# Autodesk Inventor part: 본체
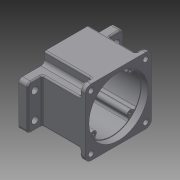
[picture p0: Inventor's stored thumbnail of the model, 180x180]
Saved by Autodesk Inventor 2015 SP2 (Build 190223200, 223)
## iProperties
Created: 2015-06
Part Number: 본체
Material: 일반
Document SubType Name: Modeling
Designer: AMC
Density: 1 g/cm^3
Appearance: 기본값
Author: AMC
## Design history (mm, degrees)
sketch "스케치1"
  geometry: L1 (0, 0)-(90, 0); L2 (90, 0)-(90, 90); L3 (90, 90)-(0, 90); L4 (0, 90)-(0, 0)
  constraints: 8 end point, 2 parallel, 1 horizontal, 1 perpendicular
  dimensions: "d0" = 90 distance of L3.end L2.end; "d1" = 90 distance of L2.end L1.end
extrude "돌출1" new body sketch "스케치1" distance "d2" = 58; taper "d3" = 0 deg
sketch "스케치2"
  geometry: L1 (0, 0)-(-90, 0) reference; L2 (-90, 0)-(-90, 90) reference; L3 (-90, 90)-(0, 90) reference; L4 (0, 90)-(0, 0) reference; L5 (20, 75)-(20, 15); L6 (-110, 15)-(-110, 75); L7 (-90, 90)-(0, 90) reference; L8 (0, 0)-(-90, 0) reference; L9 (-75, 90)-(-15, 90); L10 (-15, 0)-(-75, 0); L11 (-110, 75)-(-75, 75); L12 (-15, 75)-(20, 75); L13 (20, 15)-(-15, 15); L14 (-75, 15)-(-110, 15); L15 (-75, 0)-(-75, 15); L16 (-75, 75)-(-75, 90); L17 (-15, 90)-(-15, 75); L18 (-15, 15)-(-15, 0); 10 further points
  constraints: 24 end point, 10 parallel, 8 midpoint, 4 perpendicular, 3 horizontal, 2 horizontal alignment, 2 point on line, 2 vertical alignment, 1 coincident
  dimensions: "d4" = 130 distance of L5.end L6.start; "d5" = 60 distance of L5.start L5.end; "d6" = 60 distance of L10.start L10.end; "d7" = 35 distance between parallel lines of L6 L16; "d8" = 60 distance of L6.start L6.end; "d9" = 90 distance of L10.start L9.end; "d10" = 35 distance between parallel lines of L5 L18
extrude "돌출2" join sketch "스케치2" distance "d11" = 12; taper "d12" = 0 deg
fillet "모깎기1" dims "d13" = 8
fillet "모깎기2" dims "d14" = 5
sketch "스케치3"
  geometry: L1 (-75, 80)-(-75, 90) reference; L2 (-75, 90)-(-82, 90) reference; L3 (-90, 82)-(-90, 75) reference; L4 (-90, 75)-(-80, 75) reference; L5 (-80, 15)-(-90, 15) reference; L6 (-90, 15)-(-90, 8) reference; L7 (-82, 0)-(-75, 0) reference; L8 (-75, 0)-(-75, 10) reference; L9 (-15, 10)-(-15, 0) reference; L10 (-15, 0)-(-8, 0) reference; L11 (0, 8)-(0, 15) reference; L12 (0, 15)-(-10, 15) reference; L13 (-10, 75)-(0, 75) reference; L14 (0, 75)-(0, 82) reference; L15 (-8, 90)-(-15, 90) reference; L16 (-15, 90)-(-15, 80) reference; A1 r 5 centre (-80, 80) between (-80, 75) and (-75, 80) reference; A2 r 8 centre (-82, 82) between (-82, 90) and (-90, 82) reference; A3 r 5 centre (-80, 10) between (-75, 10) and (-80, 15) reference; A4 r 8 centre (-82, 8) between (-90, 8) and (-82, 0) reference; A5 r 5 centre (-10, 10) between (-10, 15) and (-15, 10) reference; A6 r 8 centre (-8, 8) between (-8, 0) and (0, 8) reference; A7 r 5 centre (-10, 80) between (-15, 80) and (-10, 75) reference; A8 r 8 centre (-8, 82) between (0, 82) and (-8, 90) reference; 1 further point
extrude "돌출3" cut sketch "스케치3" distance "d15" = 51; taper "d16" = 0 deg
sketch "스케치4"
  geometry: L1 (75, 90)-(75, 80) reference; L2 (80, 75)-(110, 75) reference; L3 (110, 75)-(110, 15) reference; L4 (110, 15)-(80, 15) reference; L5 (75, 10)-(75, 0) reference; L6 (75, 0)-(15, 0) reference; L7 (15, 0)-(15, 10) reference; L8 (10, 15)-(-20, 15) reference; L9 (-20, 15)-(-20, 75) reference; L10 (-20, 75)-(10, 75) reference; L11 (15, 80)-(15, 90) reference; L12 (15, 90)-(75, 90) reference; L13 (0, 15)-(0, 75) reference; A1 r 5 centre (80, 80) between (75, 80) and (80, 75) reference; A2 r 5 centre (80, 10) between (80, 15) and (75, 10) reference; A3 r 5 centre (10, 10) between (15, 10) and (10, 15) reference; A4 r 5 centre (10, 80) between (10, 75) and (15, 80) reference; 4 further points
  constraints: 2 midpoint, 1 horizontal alignment, 1 vertical alignment
hole "구멍1" sketch "스케치4" at (45, 45) diameter "d17" = 78; stored, may be unused: countersink angle "d21" = 90 deg, drill point angle "d23" = 0 deg; dims "d18" = 6, "d19" = 80, "d20" = 9, "d22" = 61
fillet "모깎기3" dims "d24" = 5
sketch "스케치5"
  geometry: L1 (-82, 90)-(-8, 90) reference; L2 (-45, 90)-(-45, 0); L3 (-110, 70)-(-110, 20) reference; L4 (-90, 75)-(-105, 75) reference; C1 r 4.5 at (-100, 62.5); C2 r 4.5 at (-100, 27.5); C3 r 4.5 at (10, 62.5); C4 r 4.5 at (10, 27.5); 1 further point
  constraints: 4 centre point, 2 end point, 2 symmetric about line, 1 midpoint, 1 vertical, 2 other
  dimensions: "d25" = 9 diameter of C1; "d26" = 9 diameter of C2; "d27" = 35 distance of C2.centre C1.centre; "d29" = 10 distance from line of C1.centre L3; "d30" = 10 distance from line of L3 C2.centre; "d31" = 12.5 distance from line of C1.centre L4
extrude "돌출4" cut sketch "스케치5" stored distance "d33" = 51; taper "d34" = 0 deg
sketch "스케치6"
  geometry: L1 (-75, 90)-(-75, 80) reference; L2 (-82, 90)-(-75, 90) reference; L3 (-90, 75)-(-90, 82) reference; L4 (-80, 75)-(-90, 75) reference; L5 (0, 75)-(-10, 75) reference; L6 (0, 82)-(0, 75) reference; L7 (-15, 90)-(-8, 90) reference; L8 (-15, 80)-(-15, 90) reference; L9 (-15, 0)-(-15, 10) reference; L10 (-8, 0)-(-15, 0) reference; L11 (0, 15)-(0, 8) reference; L12 (-10, 15)-(0, 15) reference; L13 (-90, 15)-(-80, 15) reference; L14 (-90, 8)-(-90, 15) reference; L15 (-75, 0)-(-82, 0) reference; L16 (-75, 10)-(-75, 0) reference; C1 r 3.5 at (-82, 82); C2 r 3.5 at (-8, 82); C3 r 3.5 at (-8, 8); C4 r 3.5 at (-82, 8); A1 r 5 centre (-80, 80) between (-80, 75) and (-75, 80) reference; A2 r 8 centre (-82, 82) between (-82, 90) and (-90, 82) reference; A3 r 5 centre (-10, 80) between (-15, 80) and (-10, 75) reference; A4 r 8 centre (-8, 82) between (0, 82) and (-8, 90) reference; A5 r 5 centre (-10, 10) between (-10, 15) and (-15, 10) reference; A6 r 8 centre (-8, 8) between (-8, 0) and (0, 8) reference; A7 r 5 centre (-80, 10) between (-75, 10) and (-80, 15) reference; A8 r 8 centre (-82, 8) between (-90, 8) and (-82, 0) reference; 1 further point
  constraints: 4 centre point, 4 coincident
  dimensions: "d35" = 7 diameter of C1; "d36" = 7 diameter of C2; "d37" = 7 diameter of C3; "d38" = 7 diameter of C4
extrude "돌출5" cut sketch "스케치6" stored distance "d39" = 51; taper "d40" = 0 deg
sketch "스케치7"
  geometry: L1 (0, 0)-(0, 66.237); L2 (0, 0)-(-52.363, 52.363); L3 (-21.763, 27.411)-(-25.096, 31.148); L4 (-27.411, 21.763)-(-31.148, 25.096); C1 r 39 at (0, 0) reference; A1 r 40 centre (0, 0) between (-31.148, 25.096) and (-25.096, 31.148) reference; A2 r 35 centre (0, 0) between (-24.749, 24.749) and (-21.763, 27.411); A3 r 4 centre (-24.749, 24.749) between (-27.411, 21.763) and (-21.763, 27.411); 1 further point
  constraints: 8 end point, 7 point on circle, 2 centre point, 2 coincident, 2 tangent, 1 point on line, 1 vertical
  dimensions: "d41" = 70 diameter of A2; "d42" = 45 deg angle of L1 L2; "d43" = 8 diameter of A3
extrude "돌출6" join sketch "스케치7" stored distance "d44" = 51; taper "d45" = 0 deg
fillet "모깎기4" dims "d49" = 3.5
fillet "모깎기5" dims "d50" = 2
sketch "스케치8"
  geometry: L1 (-27.507, 21.849)-(-27.411, 21.763) reference; L2 (-21.763, 27.411)-(-21.849, 27.507) reference; L3 (21.849, 27.507)-(21.763, 27.411) reference; L4 (27.411, 21.763)-(27.507, 21.849) reference; L5 (27.507, -21.849)-(27.411, -21.763) reference; L6 (21.763, -27.411)-(21.849, -27.507) reference; L7 (-21.849, -27.507)-(-21.763, -27.411) reference; L8 (-27.411, -21.763)-(-27.507, -21.849) reference; C1 r 40 at (0, 0) reference; A1 r 3.5 centre (-29.836, 19.237) between (-27.507, 21.849) and (-32.778, 21.133) reference; A2 r 4 centre (-24.749, 24.749) between (-27.411, 21.763) and (-21.763, 27.411) reference; A3 r 3.5 centre (-19.237, 29.836) between (-21.133, 32.778) and (-21.849, 27.507) reference; A4 r 39 centre (0, 0) between (21.133, 32.778) and (-21.133, 32.778) reference; A5 r 3.5 centre (19.237, 29.836) between (21.849, 27.507) and (21.133, 32.778) reference; A6 r 4 centre (24.749, 24.749) between (21.763, 27.411) and (27.411, 21.763) reference; A7 r 3.5 centre (29.836, 19.237) between (32.778, 21.133) and (27.507, 21.849) reference; A8 r 39 centre (0, 0) between (32.778, -21.133) and (32.778, 21.133) reference; A9 r 3.5 centre (29.836, -19.237) between (27.507, -21.849) and (32.778, -21.133) reference; A10 r 4 centre (24.749, -24.749) between (27.411, -21.763) and (21.763, -27.411) reference; A11 r 3.5 centre (19.237, -29.836) between (21.133, -32.778) and (21.849, -27.507) reference; A12 r 39 centre (0, 0) between (-21.133, -32.778) and (21.133, -32.778) reference; A13 r 3.5 centre (-19.237, -29.836) between (-21.849, -27.507) and (-21.133, -32.778) reference; A14 r 4 centre (-24.749, -24.749) between (-21.763, -27.411) and (-27.411, -21.763) reference; A15 r 3.5 centre (-29.836, -19.237) between (-32.778, -21.133) and (-27.507, -21.849) reference; A16 r 39 centre (0, 0) between (-32.778, 21.133) and (-32.778, -21.133) reference; 1 further point
hole "구멍2" sketch "스케치8" at (24.749, -24.749), (24.749, 24.749), (-24.749, 24.749), (-24.749, -24.749) diameter "d51" = 3.242; stored, may be unused: countersink angle "d55" = 90 deg, drill point angle "d57" = 118 deg; dims "d52" = 12, "d53" = 80, "d54" = 9, "d56" = 15
sketch "스케치9"
  geometry: L1 (20.271, -28.742)-(20.356, -28.838) reference; L2 (28.838, -20.356)-(28.742, -20.271) reference; L3 (28.742, 20.271)-(28.838, 20.356) reference; L4 (20.356, 28.838)-(20.271, 28.742) reference; L5 (-20.271, 28.742)-(-20.356, 28.838) reference; L6 (-28.838, 20.356)-(-28.742, 20.271) reference; L7 (-28.742, -20.271)-(-28.838, -20.356) reference; L8 (-20.356, -28.838)-(-20.271, -28.742) reference; A1 r 20.5 centre (0, 11) between (7.402, -8.117) and (-7.402, -8.117); A2 r 37 centre (0, 0) between (-20.049, -31.097) and (20.049, -31.097) reference; A3 r 6 centre (24.749, -24.749) between (28.742, -20.271) and (20.271, -28.742) reference; A4 r 37 centre (0, 0) between (31.097, -20.049) and (31.097, 20.049) reference; A5 r 6 centre (24.749, 24.749) between (20.271, 28.742) and (28.742, 20.271) reference; A6 r 37 centre (0, 0) between (20.049, 31.097) and (-20.049, 31.097) reference; A7 r 6 centre (-24.749, 24.749) between (-28.742, 20.271) and (-20.271, 28.742) reference; A8 r 37 centre (0, 0) between (-31.097, 20.049) and (-31.097, -20.049) reference; A9 r 6 centre (-24.749, -24.749) between (-20.271, -28.742) and (-28.742, -20.271) reference; A10 r 14 centre (0, -20) between (-7.402, -8.117) and (7.402, -8.117); A11 r 1.5 centre (19.237, -29.836) between (20.049, -31.097) and (20.356, -28.838) reference; A12 r 1.5 centre (29.836, -19.237) between (28.838, -20.356) and (31.097, -20.049) reference; A13 r 1.5 centre (29.836, 19.237) between (31.097, 20.049) and (28.838, 20.356) reference; A14 r 1.5 centre (19.237, 29.836) between (20.356, 28.838) and (20.049, 31.097) reference; A15 r 1.5 centre (-19.237, 29.836) between (-20.049, 31.097) and (-20.356, 28.838) reference; A16 r 1.5 centre (-29.836, 19.237) between (-28.838, 20.356) and (-31.097, 20.049) reference; A17 r 1.5 centre (-29.836, -19.237) between (-31.097, -20.049) and (-28.838, -20.356) reference; A18 r 1.5 centre (-19.237, -29.836) between (-20.356, -28.838) and (-20.049, -31.097) reference; 1 further point
  constraints: 4 point on circle, 2 centre point, 2 vertical alignment
  dimensions: "d58" = 41 diameter of A1; "d59" = 28 diameter of A10; "d60" = 11 distance of A2.centre A1.centre; "d61" = 20 distance of A2.centre A10.centre
extrude "돌출7" join sketch "스케치9" distance "d62" = 7; taper "d63" = 0 deg
sketch "스케치10"
  geometry: C1 r 25 at (-45, 56); A1 r 20.5 centre (-45, 56) between (-37.598, 36.883) and (-52.402, 36.883) reference; 1 further point
  constraints: 1 centre point, 1 coincident
  dimensions: "d64" = 50 diameter of C1
extrude "돌출8" join sketch "스케치10" distance "d65" = 7; taper "d66" = 0 deg
sketch "스케치11"
  geometry: C1 r 25 at (0, 0) reference; 1 further point
hole "구멍3" sketch "스케치11" at (0, 0) diameter "d67" = 25; stored, may be unused: countersink angle "d71" = 90 deg, drill point angle "d73" = 0 deg; dims "d68" = 12, "d69" = 32, "d70" = 8, "d72" = 13
sketch "스케치12"
  geometry: C1 r 12.5 at (0, 11) reference; A1 r 14 centre (0, -20) between (-7.402, -8.117) and (7.402, -8.117) reference; A2 r 20.5 centre (0, 11) between (7.402, -8.117) and (-7.402, -8.117) reference; 1 further point
hole "구멍4" sketch "스케치12" at (0, -20) diameter "d74" = 19; stored, may be unused: countersink angle "d78" = 90 deg, drill point angle "d80" = 0 deg; dims "d75" = 12, "d76" = 22, "d77" = 7, "d79" = 8
sketch "스케치13"
  geometry: C1 r 11 at (0, -20) reference; C2 r 12.5 at (0, 11) reference; C3 r 17.5 at (0, 11); A1 r 14 centre (0, -20) between (-7.402, -8.117) and (7.402, -8.117) reference; A2 r 20.5 centre (0, 11) between (7.402, -8.117) and (-7.402, -8.117) reference; 1 further point
  constraints: 1 centre point, 1 coincident
  dimensions: "d81" = 35 diameter of C3
extrude "돌출9" cut sketch "스케치13" distance "d82" = 10; taper "d83" = 0 deg
chamfer "모따기1" distance "d84" = 1; stored, may be unused: second distance "d85" = 2, angle "d86" = 45 deg
fillet "모깎기6" dims "d87" = 0.3
fillet "모깎기7" dims "d88" = 2
fillet "모깎기8" dims "d89" = 3
fillet "모깎기9" dims "d90" = 2
fillet "모깎기10" dims "d91" = 2
fillet "모깎기11" dims "d92" = 2
sketch "스케치14"
  geometry: L1 (-75, 0)-(-15, 0) reference; 3 further points
  constraints: 1 midpoint, 1 vertical alignment, 1 other
  dimensions: "d93" = 15 distance from line of L1 point (-45, 15)
feature "엠보싱1" sketch "스케치14" dims "d0" = 90, "d1" = 90, "d4" = 130, "d5" = 60, "d6" = 60, "d7" = 35, "d8" = 60, "d9" = 90, "d10" = 35, "d94" = 0.5, "d95" = 0
fillet "모깎기12" dims "d96" = 2
fillet "모깎기13" dims "d97" = 2
fillet "모깎기14" dims "d98" = 2
node "솔리드1"
pattern_circular "원형 패턴1" dims angle "d47" = 360 deg
node "투영된 루프1"
node "투영된 루프2"
node "투영된 루프3"
node "투영된 루프4"
node "투영된 루프5"
node "투영된 루프6"
node "투영된 루프7"
node "투영된 루프8"
node "투영된 루프9"
node "투영된 루프10"
node "투영된 루프11"
node "투영된 루프12"
node "투영된 루프13"
node "투영된 루프14"
node "투영된 루프15"
